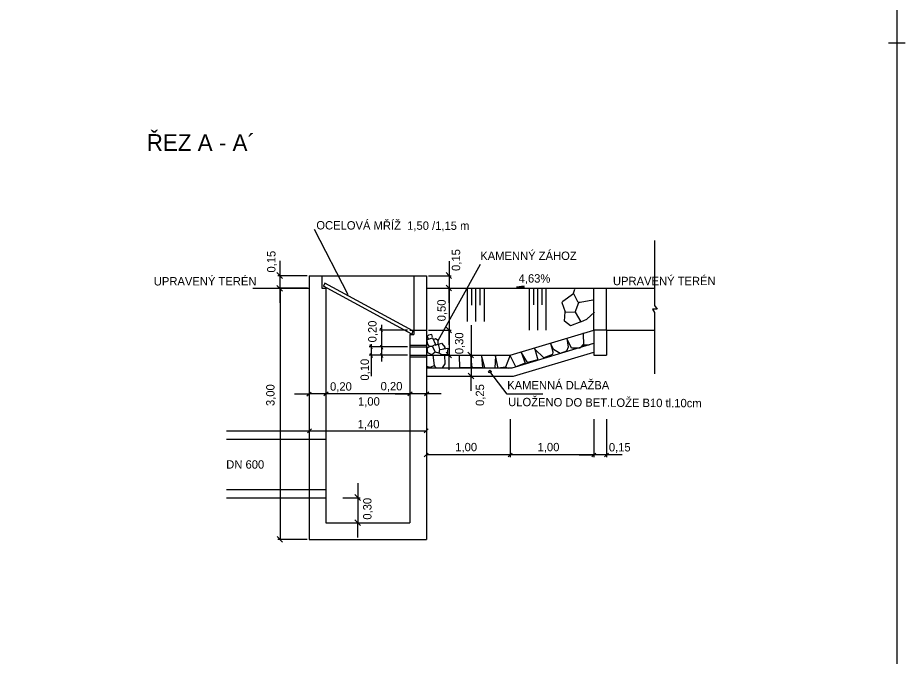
# Model space of a CAD drawing. Extents: x -463166.8 to -463145.6, y -1105023 to -1104993.1.
# Drawn here: x -463156.18 to -463145.58, y -1105015.35 to -1105007.73 of the extents above; entities that cross this region are included whole.
import ezdxf

# ---------------------------------------------------------------- set-up
doc = ezdxf.new("R2010")
doc.units = 0
doc.layers.add('Vrstva 14', color=7, linetype='Continuous')
doc.layers.add('Vrstva 57', color=7, linetype='Continuous')

msp = doc.modelspace()

# ---------------------------------------------------------------- linework, layer by layer
at = {"layer": 'Vrstva 14'}
for p, q in [((-463145.676, -1105007.928), (-463145.676, -1105008.128)), ((-463145.676, -1105007.928), (-463145.676, -1105008.128)), ((-463145.676, -1105007.928), (-463145.676, -1105008.128)), ((-463145.676, -1105007.928), (-463145.676, -1105008.128)), ((-463145.776, -1105008.028), (-463145.576, -1105008.028)), ((-463145.776, -1105008.028), (-463145.576, -1105008.028)), ((-463145.776, -1105008.028), (-463145.576, -1105008.028)), ((-463145.776, -1105008.028), (-463145.576, -1105008.028)), ((-463152.635, -1105010.253), (-463152.233, -1105011.032)), ((-463153.044, -1105010.631), (-463153.044, -1105011.134)), ((-463151.153, -1105011.581), (-463150.651, -1105010.669)), ((-463151.025, -1105010.633), (-463151.025, -1105010.809)), ((-463153.08, -1105010.772), (-463153.013, -1105010.841)), ((-463151.061, -1105010.772), (-463150.994, -1105010.841)), ((-463152.72, -1105010.809), (-463153.069, -1105010.809)), ((-463152.695, -1105010.809), (-463152.545, -1105010.809)), ((-463152.695, -1105010.809), (-463152.695, -1105012.053)), ((-463152.545, -1105010.809), (-463151.445, -1105010.809)), ((-463152.545, -1105010.809), (-463152.545, -1105010.959)), ((-463151.445, -1105010.809), (-463151.295, -1105010.809)), ((-463151.445, -1105010.809), (-463151.445, -1105011.509)), ((-463151.295, -1105010.809), (-463151.295, -1105011.459)), ((-463151.27, -1105010.809), (-463151, -1105010.809)), ((-463151.025, -1105010.784), (-463151.025, -1105010.959)), ((-463151.025, -1105010.809), (-463151.025, -1105010.959)), ((-463153.368, -1105010.959), (-463152.695, -1105010.959)), ((-463153.08, -1105010.925), (-463153.013, -1105010.994)), ((-463152.72, -1105010.959), (-463153.069, -1105010.959)), ((-463152.716, -1105010.959), (-463153.068, -1105010.959)), ((-463153.043, -1105010.959), (-463153.043, -1105013.96)), ((-463152.545, -1105010.959), (-463152.495, -1105010.959)), ((-463152.508, -1105010.896), (-463152.523, -1105010.935)), ((-463151.471, -1105011.505), (-463152.523, -1105010.935)), ((-463151.456, -1105011.466), (-463152.508, -1105010.896)), ((-463152.495, -1105010.959), (-463152.495, -1105012.053)), ((-463151.295, -1105010.959), (-463148.579, -1105010.959)), ((-463151.27, -1105010.959), (-463151, -1105010.959)), ((-463151.061, -1105010.922), (-463150.994, -1105010.991)), ((-463151.025, -1105011.134), (-463151.025, -1105010.959)), ((-463151.025, -1105010.959), (-463151.025, -1105011.459)), ((-463150.807, -1105010.968), (-463150.807, -1105011.356)), ((-463150.757, -1105010.968), (-463150.757, -1105011.159)), ((-463150.707, -1105010.968), (-463150.707, -1105011.356)), ((-463150.657, -1105010.968), (-463150.657, -1105011.159)), ((-463150.607, -1105010.968), (-463150.607, -1105011.356)), ((-463150.221, -1105010.943), (-463150.127, -1105010.931)), ((-463150.221, -1105010.943), (-463150.125, -1105010.943)), ((-463150.068, -1105010.964), (-463150.068, -1105011.459)), ((-463150.018, -1105010.964), (-463150.018, -1105011.155)), ((-463149.968, -1105010.964), (-463149.968, -1105011.459)), ((-463149.918, -1105010.964), (-463149.918, -1105011.155)), ((-463149.868, -1105010.964), (-463149.868, -1105011.459)), ((-463149.295, -1105011.459), (-463149.295, -1105010.959)), ((-463149.145, -1105011.459), (-463149.145, -1105010.959)), ((-463151.025, -1105011.284), (-463151.025, -1105011.459)), ((-463151.83, -1105011.397), (-463151.83, -1105011.834)), ((-463150.76, -1105011.401), (-463150.76, -1105011.759)), ((-463151.52, -1105011.459), (-463151.855, -1105011.459)), ((-463151.818, -1105011.484), (-463151.842, -1105011.434)), ((-463151.495, -1105011.459), (-463151.295, -1105011.459)), ((-463151.495, -1105011.509), (-463151.445, -1105011.509)), ((-463151.495, -1105011.509), (-463151.495, -1105012.053)), ((-463151.456, -1105011.466), (-463151.471, -1105011.505)), ((-463151.295, -1105011.459), (-463151.295, -1105012.053)), ((-463151.27, -1105011.459), (-463151, -1105011.459)), ((-463151.061, -1105011.422), (-463150.994, -1105011.491)), ((-463151.025, -1105011.634), (-463151.025, -1105011.459)), ((-463151.025, -1105011.459), (-463151.025, -1105011.759)), ((-463150.295, -1105011.759), (-463149.295, -1105011.459)), ((-463149.295, -1105011.459), (-463149.295, -1105011.759)), ((-463149.145, -1105011.459), (-463149.295, -1105011.459)), ((-463149.145, -1105011.459), (-463148.579, -1105011.459)), ((-463149.145, -1105011.459), (-463149.145, -1105011.759)), ((-463151.955, -1105011.626), (-463151.955, -1105012.008)), ((-463150.272, -1105011.909), (-463149.295, -1105011.616)), ((-463151.855, -1105011.659), (-463151.98, -1105011.659)), ((-463151.942, -1105011.684), (-463151.968, -1105011.634)), ((-463151.52, -1105011.659), (-463151.855, -1105011.659)), ((-463151.842, -1105011.634), (-463151.818, -1105011.684)), ((-463151.495, -1105011.639), (-463151.295, -1105011.639)), ((-463151.495, -1105011.659), (-463151.295, -1105011.659)), ((-463151.061, -1105011.721), (-463150.994, -1105011.79)), ((-463150.801, -1105011.721), (-463150.734, -1105011.79)), ((-463150.256, -1105012.009), (-463149.295, -1105011.721)), ((-463152.695, -1105011.793), (-463152.695, -1105012.243)), ((-463152.495, -1105011.791), (-463152.495, -1105012.244)), ((-463152.495, -1105011.793), (-463152.495, -1105012.243)), ((-463151.52, -1105011.759), (-463151.98, -1105011.759)), ((-463151.968, -1105011.734), (-463151.942, -1105011.784)), ((-463151.842, -1105011.734), (-463151.818, -1105011.784)), ((-463151.83, -1105011.759), (-463151.83, -1105011.82)), ((-463151.495, -1105011.759), (-463151.295, -1105011.759)), ((-463151.495, -1105011.779), (-463151.295, -1105011.779)), ((-463151.495, -1105011.791), (-463151.495, -1105012.244)), ((-463151.495, -1105011.795), (-463151.495, -1105012.245)), ((-463151.295, -1105011.759), (-463150.295, -1105011.759)), ((-463151.295, -1105011.795), (-463151.295, -1105012.245)), ((-463151.27, -1105011.759), (-463151, -1105011.759)), ((-463151.025, -1105011.934), (-463151.025, -1105011.759)), ((-463151, -1105011.759), (-463150.875, -1105011.759)), ((-463150.76, -1105011.759), (-463150.76, -1105012.009)), ((-463149.295, -1105011.759), (-463149.145, -1105011.759)), ((-463151.295, -1105011.909), (-463150.272, -1105011.909)), ((-463151.295, -1105012.009), (-463150.256, -1105012.009)), ((-463151.27, -1105012.009), (-463150.875, -1105012.009)), ((-463150.796, -1105011.972), (-463150.729, -1105012.041)), ((-463150.76, -1105012.184), (-463150.76, -1105012.009)), ((-463150.331, -1105012.222), (-463150.537, -1105011.953)), ((-463152.695, -1105012.053), (-463152.695, -1105013.96)), ((-463152.495, -1105012.053), (-463152.495, -1105013.76)), ((-463151.495, -1105012.053), (-463151.495, -1105013.76)), ((-463151.295, -1105012.053), (-463151.295, -1105013.96)), ((-463152.87, -1105012.218), (-463152.695, -1105012.218)), ((-463152.722, -1105012.243), (-463152.673, -1105012.198)), ((-463152.495, -1105012.218), (-463152.695, -1105012.218)), ((-463152.52, -1105012.241), (-463152.47, -1105012.195)), ((-463152.32, -1105012.218), (-463152.495, -1105012.218)), ((-463151.495, -1105012.219), (-463152.495, -1105012.219)), ((-463151.67, -1105012.22), (-463151.495, -1105012.22)), ((-463151.517, -1105012.241), (-463151.467, -1105012.195)), ((-463151.295, -1105012.22), (-463151.495, -1105012.22)), ((-463151.316, -1105012.241), (-463151.266, -1105012.195)), ((-463151.12, -1105012.22), (-463151.295, -1105012.22)), ((-463149.903, -1105012.222), (-463150.331, -1105012.222)), ((-463152.695, -1105012.43), (-463152.695, -1105012.689)), ((-463151.295, -1105012.43), (-463151.295, -1105012.689)), ((-463151.295, -1105012.524), (-463151.295, -1105012.974)), ((-463150.295, -1105012.522), (-463150.295, -1105012.974)), ((-463149.295, -1105012.522), (-463149.295, -1105012.974)), ((-463149.145, -1105012.522), (-463149.145, -1105012.974)), ((-463153.681, -1105012.66), (-463152.495, -1105012.66)), ((-463152.717, -1105012.684), (-463152.668, -1105012.639)), ((-463151.295, -1105012.664), (-463152.695, -1105012.664)), ((-463151.323, -1105012.684), (-463151.273, -1105012.639)), ((-463153.681, -1105012.76), (-463152.495, -1105012.76)), ((-463151.323, -1105012.972), (-463151.273, -1105012.927)), ((-463150.295, -1105012.949), (-463151.295, -1105012.949)), ((-463150.319, -1105012.972), (-463150.269, -1105012.927)), ((-463149.295, -1105012.949), (-463150.295, -1105012.949)), ((-463149.47, -1105012.949), (-463149.295, -1105012.949)), ((-463149.32, -1105012.972), (-463149.27, -1105012.927)), ((-463149.145, -1105012.949), (-463149.295, -1105012.949)), ((-463149.17, -1105012.972), (-463149.12, -1105012.927)), ((-463148.958, -1105012.949), (-463149.145, -1105012.949)), ((-463152.113, -1105013.285), (-463152.113, -1105013.46)), ((-463153.681, -1105013.36), (-463152.495, -1105013.36)), ((-463152.149, -1105013.423), (-463152.082, -1105013.492)), ((-463153.681, -1105013.46), (-463152.495, -1105013.46)), ((-463152.294, -1105013.46), (-463152.088, -1105013.46)), ((-463152.113, -1105013.46), (-463152.113, -1105013.76)), ((-463152.149, -1105013.723), (-463152.082, -1105013.792)), ((-463152.495, -1105013.76), (-463151.495, -1105013.76)), ((-463152.494, -1105013.76), (-463152.088, -1105013.76)), ((-463152.113, -1105013.935), (-463152.113, -1105013.76)), ((-463153.079, -1105013.923), (-463153.012, -1105013.992)), ((-463152.72, -1105013.96), (-463153.068, -1105013.96)), ((-463152.695, -1105013.96), (-463151.295, -1105013.96))]:
    msp.add_line(p, q, dxfattribs=at)
msp.add_lwpolyline([(-463166.676, -1104993.178), (-463145.676, -1104993.178), (-463145.676, -1105022.878), (-463166.676, -1105022.878)], close=True, dxfattribs=at)
for points in [[(-463148.569, -1105010.39), (-463148.57, -1105011.165), (-463148.541, -1105011.208), (-463148.569, -1105011.207), (-463148.594, -1105011.207), (-463148.569, -1105011.249), (-463148.569, -1105011.979)], [(-463149.307, -1105011.099), (-463149.457, -1105011.129), (-463149.483, -1105011.129), (-463149.539, -1105011.017), (-463149.524, -1105010.968)], [(-463149.539, -1105011.024), (-463149.666, -1105011.118), (-463149.677, -1105011.129), (-463149.636, -1105011.241), (-463149.52, -1105011.245), (-463149.475, -1105011.129)], [(-463149.449, -1105011.361), (-463149.576, -1105011.409), (-463149.644, -1105011.353), (-463149.636, -1105011.241)], [(-463149.52, -1105011.245), (-463149.449, -1105011.361), (-463149.378, -1105011.327), (-463149.288, -1105011.245)], [(-463151.224, -1105011.544), (-463151.232, -1105011.51), (-463151.269, -1105011.518), (-463151.288, -1105011.533), (-463151.269, -1105011.57)], [(-463149.421, -1105011.492), (-463149.417, -1105011.646), (-463149.414, -1105011.634), (-463149.35, -1105011.634)], [(-463151.284, -1105011.57), (-463151.224, -1105011.551), (-463151.187, -1105011.63), (-463151.232, -1105011.656), (-463151.265, -1105011.649), (-463151.284, -1105011.615), (-463151.288, -1105011.574)], [(-463151.153, -1105011.626), (-463151.153, -1105011.581), (-463151.187, -1105011.563), (-463151.213, -1105011.574)], [(-463151.191, -1105011.637), (-463151.153, -1105011.626), (-463151.138, -1105011.69), (-463151.146, -1105011.735), (-463151.187, -1105011.723)], [(-463151.153, -1105011.63), (-463151.116, -1105011.615), (-463151.071, -1105011.667), (-463151.09, -1105011.686)], [(-463149.813, -1105011.616), (-463149.787, -1105011.717), (-463149.791, -1105011.75), (-463149.891, -1105011.791), (-463150, -1105011.687), (-463150, -1105011.668)], [(-463149.619, -1105011.56), (-463149.604, -1105011.661), (-463149.623, -1105011.709), (-463149.697, -1105011.739), (-463149.776, -1105011.69), (-463149.813, -1105011.616)], [(-463149.417, -1105011.627), (-463149.462, -1105011.672), (-463149.563, -1105011.675), (-463149.619, -1105011.56)], [(-463151.254, -1105011.649), (-463151.224, -1105011.656), (-463151.191, -1105011.72), (-463151.232, -1105011.753), (-463151.28, -1105011.731), (-463151.288, -1105011.675), (-463151.254, -1105011.645)], [(-463151.131, -1105011.69), (-463151.041, -1105011.675), (-463151.049, -1105011.753), (-463151.105, -1105011.753), (-463151.149, -1105011.731)], [(-463150.164, -1105011.72), (-463150.115, -1105011.855), (-463150.227, -1105011.896), (-463150.295, -1105011.761), (-463150.295, -1105011.759)], [(-463150, -1105011.687), (-463149.966, -1105011.814), (-463150.089, -1105011.847), (-463150.164, -1105011.72)], [(-463151.079, -1105011.758), (-463151.076, -1105011.863), (-463151.108, -1105011.91), (-463151.178, -1105011.911), (-463151.199, -1105011.88), (-463151.214, -1105011.759)], [(-463150.765, -1105011.758), (-463150.765, -1105011.911), (-463150.772, -1105011.907), (-463150.895, -1105011.907), (-463150.899, -1105011.761)], [(-463150.638, -1105011.761), (-463150.627, -1105011.907), (-463150.75, -1105011.903), (-463150.765, -1105011.758)], [(-463150.47, -1105011.765), (-463150.477, -1105011.914), (-463150.597, -1105011.907), (-463150.638, -1105011.761), (-463150.638, -1105011.754)], [(-463150.351, -1105011.9), (-463150.44, -1105011.914), (-463150.47, -1105011.765), (-463150.47, -1105011.754)], [(-463150.295, -1105011.759), (-463150.351, -1105011.9), (-463150.309, -1105011.911)], [(-463151.199, -1105011.88), (-463151.251, -1105011.906), (-463151.291, -1105011.891)]]:
    msp.add_lwpolyline(points, dxfattribs=at)
msp.add_circle((-463150.537, -1105011.953), 0.0146, dxfattribs=at)

# ---------------------------------------------------------------- texts
for s, p in [('0,15', (-463153.098, -1105010.771)), ('0,15', (-463150.892, -1105010.752)), ('0,50', (-463151.065, -1105011.353)), ('0,20', (-463151.891, -1105011.605)), ('0,30', (-463150.854, -1105011.746)), ('0,10', (-463151.982, -1105012.061)), ('3,00', (-463153.109, -1105012.365)), ('0,25', (-463150.606, -1105012.364)), ('0,30', (-463151.951, -1105013.722))]:
    msp.add_text(s, height=0.1, rotation=90, dxfattribs=at).set_placement(p)
for s, p in [('0,20', (-463152.446, -1105012.181)), ('0,20', (-463151.842, -1105012.178)), ('1,00', (-463152.112, -1105012.36)), ('1,40', (-463152.116, -1105012.631)), ('1,00', (-463150.95, -1105012.905)), ('1,00', (-463149.967, -1105012.905)), ('0,15', (-463149.116, -1105012.907))]:
    msp.add_text(s, height=0.1, dxfattribs=at).set_placement(p)
at = {"layer": 'Vrstva 57'}
for s, height, rotation, p in [('ŘEZ A - A´', 0.2, 359.9224, (-463154.636, -1105009.318)), ('OCELOVÁ MŘÍŽ  1,50 /1,15 m', 0.1, 359.7976, (-463152.61, -1105010.256)), ('KAMENNÝ ZÁHOZ', 0.1, 0.0257, (-463150.652, -1105010.621)), ('UPRAVENÝ TERÉN', 0.1, 0.0257, (-463154.551, -1105010.925)), ('4,63%', 0.1, 0.0257, (-463150.194, -1105010.891)), ('UPRAVENÝ TERÉN', 0.1, 0.0257, (-463149.067, -1105010.922)), ('KAMENNÁ DLAŽBA', 0.1, 0.0257, (-463150.33, -1105012.166)), ('ULOŽENO DO BET.LOŽE B10 tl.10cm', 0.1, 359.6238, (-463150.319, -1105012.366)), ('DN 600', 0.1, 359.903, (-463153.686, -1105013.112))]:
    msp.add_text(s, height=height, rotation=rotation, dxfattribs=at).set_placement(p)

doc.saveas('drawing.dxf')
